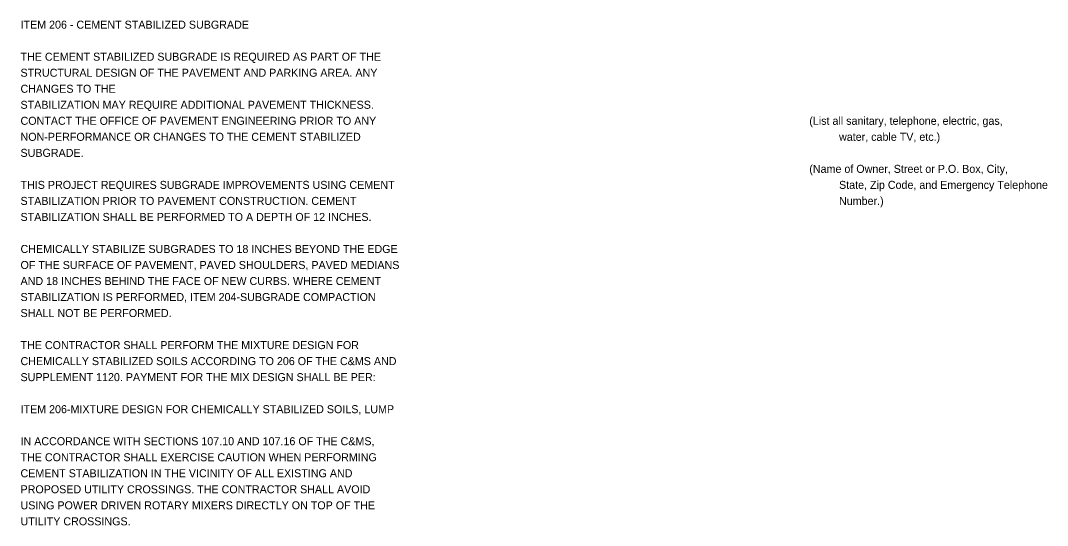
# Model space of a CAD drawing. Extents: x -19 to 64.6, y -1.7 to 22.
# Drawn here: x -18.96 to -1.01, y 12.32 to 21.14 of the extents above; entities that cross this region are included whole.
import ezdxf

# ---------------------------------------------------------------- set-up
doc = ezdxf.new("R2010")
doc.units = 0
doc.layers.add('SH_Text', color=7, linetype='Continuous')

msp = doc.modelspace()

# ---------------------------------------------------------------- texts
at = {"layer": 'SH_Text'}
for s, p in [('ITEM 206 - CEMENT STABILIZED SUBGRADE', (-18.965, 21)), ('THE CEMENT STABILIZED SUBGRADE IS REQUIRED AS PART OF THE', (-18.965, 20.44)), ('STRUCTURAL DESIGN OF THE PAVEMENT AND PARKING AREA. ANY ', (-18.965, 20.16)), ('CHANGES TO THE', (-18.965, 19.88)), ('STABILIZATION MAY REQUIRE ADDITIONAL PAVEMENT THICKNESS.', (-18.965, 19.6)), ('CONTACT THE OFFICE OF PAVEMENT ENGINEERING PRIOR TO ANY', (-18.965, 19.32)), ('    (List all sanitary, telephone, electric, gas,', (-5.379, 19.32)), ('NON-PERFORMANCE OR CHANGES TO THE CEMENT STABILIZED ', (-18.965, 19.04)), ('              water, cable TV, etc.)', (-5.379, 19.04)), ('SUBGRADE.  ', (-18.965, 18.76)), ('    (Name of Owner, Street or P.O. Box, City,', (-5.379, 18.48)), ('THIS PROJECT REQUIRES SUBGRADE IMPROVEMENTS USING CEMENT ', (-18.965, 18.2)), ('              State, Zip Code, and Emergency Telephone', (-5.379, 18.2)), ('STABILIZATION PRIOR TO PAVEMENT CONSTRUCTION. CEMENT ', (-18.965, 17.92)), ('              Number.)', (-5.379, 17.92)), ('STABILIZATION SHALL BE PERFORMED TO A DEPTH OF 12 INCHES.', (-18.965, 17.64)), ('CHEMICALLY STABILIZE SUBGRADES TO 18 INCHES BEYOND THE EDGE ', (-18.965, 17.08)), ('OF THE SURFACE OF PAVEMENT, PAVED SHOULDERS, PAVED MEDIANS ', (-18.965, 16.8)), ('AND 18 INCHES BEHIND THE FACE OF NEW CURBS. WHERE CEMENT ', (-18.965, 16.52)), ('STABILIZATION IS PERFORMED, ITEM 204-SUBGRADE COMPACTION ', (-18.965, 16.24)), ('SHALL NOT BE PERFORMED.', (-18.965, 15.96)), ('THE CONTRACTOR SHALL PERFORM THE MIXTURE DESIGN FOR ', (-18.965, 15.4)), ('CHEMICALLY STABILIZED SOILS ACCORDING TO 206 OF THE C&MS AND ', (-18.965, 15.12)), ('SUPPLEMENT 1120. PAYMENT FOR THE MIX DESIGN SHALL BE PER:', (-18.965, 14.84)), ('ITEM 206-MIXTURE DESIGN FOR CHEMICALLY STABILIZED SOILS, LUMP', (-18.965, 14.28)), ('IN ACCORDANCE WITH SECTIONS 107.10 AND 107.16 OF THE C&MS, ', (-18.965, 13.72)), ('THE CONTRACTOR SHALL EXERCISE CAUTION WHEN PERFORMING ', (-18.965, 13.44)), ('CEMENT STABILIZATION IN THE VICINITY OF ALL EXISTING AND ', (-18.965, 13.16)), ('PROPOSED UTILITY CROSSINGS. THE CONTRACTOR SHALL AVOID ', (-18.965, 12.88)), ('USING POWER DRIVEN ROTARY MIXERS DIRECTLY ON TOP OF THE ', (-18.965, 12.6)), ('UTILITY CROSSINGS.', (-18.965, 12.32))]:
    msp.add_text(s, height=0.14, dxfattribs=at).set_placement(p)

doc.saveas('drawing.dxf')
